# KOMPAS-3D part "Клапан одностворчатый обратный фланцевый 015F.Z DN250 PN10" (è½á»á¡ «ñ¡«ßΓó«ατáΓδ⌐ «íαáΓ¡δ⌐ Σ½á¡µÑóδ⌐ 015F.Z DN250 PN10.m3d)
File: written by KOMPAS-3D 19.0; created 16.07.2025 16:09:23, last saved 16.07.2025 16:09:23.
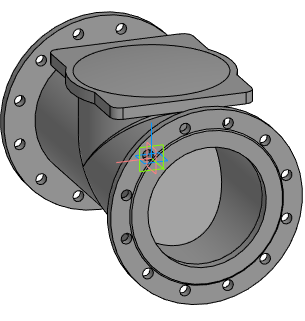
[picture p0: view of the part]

Document properties: Полное имя файла: E:\Dendor Работа Сачек\3D для проектировщиков\5.4 Тип 015F.Z. Клапан одностворчатый обратный фланцевый\stp_Клапан одностворчатый обратный фланцевый 015F.Z PN10_16\Клапан одностворчатый обратный фланцевый 015F.Z DN250 PN10.m3d

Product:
- Part/product: Клапан одностворчатый обратный фланцевый 015F.Z DN250 PN10

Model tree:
1. Операция без истории:1  (labels: Клапан одностворчатый обратный фланцевый 015F.Z DN250 PN10)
